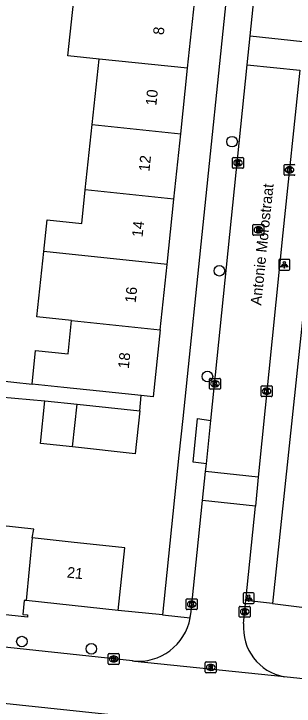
# Model space of a CAD drawing. Extents: x 163010 to 163853, y 382793 to 383982.
# Drawn here: x 163283.3 to 163309.2, y 383329.7 to 383393.8 of the extents above; entities that cross this region are included whole.
import ezdxf

# ---------------------------------------------------------------- set-up
doc = ezdxf.new("R2010")
doc.units = 0
for name, color, linetype in [('IMGEO_Boom', 7, 'Continuous'), ('IMGEO_Kolk', 7, 'Continuous'), ('IMGEO_Lichtpunt', 7, 'Continuous'), ('IMGEO_Openbare_ruimte_label', 7, 'Continuous'), ('IMGEO_Pand', 7, 'Continuous'), ('IMGEO_Pand_nummerreeks', 7, 'Continuous'), ('IMGEO_Rijbaan_lokaal_open', 7, 'Continuous'), ('IMGEO_Rioolput', 7, 'Continuous'), ('IMGEO_Voetpad_open', 7, 'Continuous')]:
    doc.layers.add(name, color=color, linetype=linetype)

msp = doc.modelspace()

# ---------------------------------------------------------------- linework, layer by layer
at = {"layer": 'IMGEO_Boom'}
for centre in [(163303.477, 383381.978), (163302.304, 383370.024), (163301.197, 383360.239), (163284.048, 383335.699), (163290.47, 383335.026)]:
    msp.add_circle(centre, 0.489, dxfattribs=at)
at = {"layer": 'IMGEO_Kolk'}
for p, q in [((163303.6, 383380.516), (163304.452, 383380.516)), ((163303.525, 383379.59), (163303.525, 383380.442)), ((163304.013, 383380.296), (163304.038, 383380.296)), ((163304.526, 383380.442), (163304.526, 383379.59)), ((163304.452, 383379.516), (163303.6, 383379.516)), ((163304.036, 383379.736), (163304.011, 383379.736)), ((163308.287, 383378.94), (163308.287, 383379.792)), ((163308.362, 383379.866), (163309.214, 383379.866)), ((163308.775, 383379.646), (163308.8, 383379.646)), ((163309.214, 383378.866), (163308.362, 383378.866)), ((163308.798, 383379.086), (163308.773, 383379.086)), ((163301.473, 383360.065), (163302.325, 383360.065)), ((163301.398, 383359.139), (163301.398, 383359.991)), ((163301.886, 383359.845), (163301.911, 383359.845)), ((163302.399, 383359.991), (163302.399, 383359.139)), ((163306.244, 383359.372), (163307.096, 383359.372)), ((163302.325, 383359.065), (163301.473, 383359.065)), ((163301.909, 383359.285), (163301.884, 383359.285)), ((163306.169, 383358.446), (163306.169, 383359.298)), ((163306.657, 383359.152), (163306.682, 383359.152)), ((163307.17, 383359.298), (163307.17, 383358.446)), ((163307.096, 383358.372), (163306.244, 383358.372)), ((163306.68, 383358.592), (163306.655, 383358.592)), ((163299.248, 383338.728), (163299.248, 383339.58)), ((163299.323, 383339.654), (163300.175, 383339.654)), ((163300.249, 383339.58), (163300.249, 383338.728)), ((163299.759, 383338.874), (163299.734, 383338.874)), ((163299.736, 383339.434), (163299.761, 383339.434)), ((163304.142, 383338.031), (163304.142, 383338.883)), ((163304.217, 383338.957), (163305.069, 383338.957)), ((163305.143, 383338.883), (163305.143, 383338.031)), ((163300.175, 383338.654), (163299.323, 383338.654)), ((163304.63, 383338.737), (163304.655, 383338.737)), ((163305.069, 383337.957), (163304.217, 383337.957)), ((163304.653, 383338.177), (163304.628, 383338.177)), ((163292.036, 383333.661), (163292.036, 383334.513)), ((163292.111, 383334.587), (163292.963, 383334.587)), ((163292.524, 383334.367), (163292.549, 383334.367)), ((163293.037, 383334.513), (163293.037, 383333.661)), ((163292.547, 383333.807), (163292.522, 383333.807)), ((163292.963, 383333.587), (163292.111, 383333.587))]:
    msp.add_line(p, q, dxfattribs=at)
for points in [[(163303.6, 383380.516), (163304.452, 383380.516)], [(163303.525, 383379.59), (163303.525, 383380.442)], [(163303.846, 383380.216), (163303.969, 383380.216), (163303.969, 383380.065), (163304.099, 383380.216), (163304.263, 383380.216), (163304.117, 383380.065), (163304.27, 383379.816), (163304.118, 383379.816), (163304.033, 383379.98), (163303.969, 383379.913), (163303.969, 383379.816), (163303.846, 383379.816), (163303.846, 383380.216)], [(163304.526, 383380.442), (163304.526, 383379.59)], [(163304.452, 383379.516), (163303.6, 383379.516)], [(163308.287, 383378.94), (163308.287, 383379.792)], [(163308.362, 383379.866), (163309.214, 383379.866)], [(163308.608, 383379.566), (163308.731, 383379.566), (163308.731, 383379.415), (163308.861, 383379.566), (163309.025, 383379.566), (163308.879, 383379.415), (163309.032, 383379.166), (163308.88, 383379.166), (163308.795, 383379.33), (163308.731, 383379.263), (163308.731, 383379.166), (163308.608, 383379.166), (163308.608, 383379.566)], [(163309.214, 383378.866), (163308.362, 383378.866)], [(163301.473, 383360.065), (163302.325, 383360.065)], [(163301.398, 383359.139), (163301.398, 383359.991)], [(163301.719, 383359.765), (163301.842, 383359.765), (163301.842, 383359.614), (163301.972, 383359.765), (163302.136, 383359.765), (163301.99, 383359.614), (163302.143, 383359.365), (163301.991, 383359.365), (163301.906, 383359.529), (163301.842, 383359.462), (163301.842, 383359.365), (163301.719, 383359.365), (163301.719, 383359.765)], [(163302.399, 383359.991), (163302.399, 383359.139)], [(163306.244, 383359.372), (163307.096, 383359.372)], [(163302.325, 383359.065), (163301.473, 383359.065)], [(163306.169, 383358.446), (163306.169, 383359.298)], [(163306.49, 383359.072), (163306.613, 383359.072), (163306.613, 383358.921), (163306.743, 383359.072), (163306.907, 383359.072), (163306.761, 383358.921), (163306.914, 383358.672), (163306.762, 383358.672), (163306.677, 383358.836), (163306.613, 383358.769), (163306.613, 383358.672), (163306.49, 383358.672), (163306.49, 383359.072)], [(163307.17, 383359.298), (163307.17, 383358.446)], [(163307.096, 383358.372), (163306.244, 383358.372)], [(163299.248, 383338.728), (163299.248, 383339.58)], [(163299.323, 383339.654), (163300.175, 383339.654)], [(163300.249, 383339.58), (163300.249, 383338.728)], [(163299.569, 383339.354), (163299.692, 383339.354), (163299.692, 383339.203), (163299.822, 383339.354), (163299.986, 383339.354), (163299.84, 383339.203), (163299.993, 383338.954), (163299.841, 383338.954), (163299.756, 383339.118), (163299.692, 383339.051), (163299.692, 383338.954), (163299.569, 383338.954), (163299.569, 383339.354)], [(163304.142, 383338.031), (163304.142, 383338.883)], [(163304.217, 383338.957), (163305.069, 383338.957)], [(163305.143, 383338.883), (163305.143, 383338.031)], [(163300.175, 383338.654), (163299.323, 383338.654)], [(163304.463, 383338.657), (163304.586, 383338.657), (163304.586, 383338.506), (163304.716, 383338.657), (163304.88, 383338.657), (163304.734, 383338.506), (163304.887, 383338.257), (163304.735, 383338.257), (163304.65, 383338.421), (163304.586, 383338.354), (163304.586, 383338.257), (163304.463, 383338.257), (163304.463, 383338.657)], [(163305.069, 383337.957), (163304.217, 383337.957)], [(163292.036, 383333.661), (163292.036, 383334.513)], [(163292.111, 383334.587), (163292.963, 383334.587)], [(163293.037, 383334.513), (163293.037, 383333.661)], [(163292.357, 383334.287), (163292.48, 383334.287), (163292.48, 383334.136), (163292.61, 383334.287), (163292.774, 383334.287), (163292.628, 383334.136), (163292.781, 383333.887), (163292.629, 383333.887), (163292.544, 383334.051), (163292.48, 383333.984), (163292.48, 383333.887), (163292.357, 383333.887), (163292.357, 383334.287)], [(163292.963, 383333.587), (163292.111, 383333.587)]]:
    msp.add_lwpolyline(points, dxfattribs=at)
for centre, start, end in [((163303.602, 383380.44), 91.55205, 178.44795), ((163303.602, 383380.44), 91.55205, 178.44795), ((163304.45, 383380.44), 1.55205, 88.44795), ((163304.45, 383380.44), 1.55205, 88.44795), ((163303.602, 383379.592), 181.55205, 268.44795), ((163303.602, 383379.592), 181.55205, 268.44795), ((163304.45, 383379.592), 271.55205, 358.44795), ((163304.45, 383379.592), 271.55205, 358.44795), ((163308.364, 383379.79), 91.55205, 178.44795), ((163308.364, 383379.79), 91.55205, 178.44795), ((163309.212, 383379.79), 1.55205, 88.44795), ((163309.212, 383379.79), 1.55205, 88.44795), ((163308.364, 383378.942), 181.55205, 268.44795), ((163308.364, 383378.942), 181.55205, 268.44795), ((163309.212, 383378.942), 271.55205, 358.44795), ((163309.212, 383378.942), 271.55205, 358.44795), ((163301.475, 383359.989), 91.55205, 178.44795), ((163301.475, 383359.989), 91.55205, 178.44795), ((163302.323, 383359.989), 1.55205, 88.44795), ((163302.323, 383359.989), 1.55205, 88.44795), ((163306.246, 383359.296), 91.55205, 178.44795), ((163306.246, 383359.296), 91.55205, 178.44795), ((163307.094, 383359.296), 1.55205, 88.44795), ((163307.094, 383359.296), 1.55205, 88.44795), ((163301.475, 383359.141), 181.55205, 268.44795), ((163301.475, 383359.141), 181.55205, 268.44795), ((163302.323, 383359.141), 271.55205, 358.44795), ((163302.323, 383359.141), 271.55205, 358.44795), ((163306.246, 383358.448), 181.55205, 268.44795), ((163306.246, 383358.448), 181.55205, 268.44795), ((163307.094, 383358.448), 271.55205, 358.44795), ((163307.094, 383358.448), 271.55205, 358.44795), ((163299.325, 383339.578), 91.55205, 178.44795), ((163299.325, 383339.578), 91.55205, 178.44795), ((163300.173, 383339.578), 1.55205, 88.44795), ((163300.173, 383339.578), 1.55205, 88.44795), ((163304.219, 383338.881), 91.55205, 178.44795), ((163304.219, 383338.881), 91.55205, 178.44795), ((163305.067, 383338.881), 1.55205, 88.44795), ((163305.067, 383338.881), 1.55205, 88.44795), ((163299.325, 383338.73), 181.55205, 268.44795), ((163299.325, 383338.73), 181.55205, 268.44795), ((163300.173, 383338.73), 271.55205, 358.44795), ((163300.173, 383338.73), 271.55205, 358.44795), ((163304.219, 383338.033), 181.55205, 268.44795), ((163304.219, 383338.033), 181.55205, 268.44795), ((163305.067, 383338.033), 271.55205, 358.44795), ((163305.067, 383338.033), 271.55205, 358.44795), ((163292.113, 383334.511), 91.55205, 178.44795), ((163292.113, 383334.511), 91.55205, 178.44795), ((163292.961, 383334.511), 1.55205, 88.44795), ((163292.961, 383334.511), 1.55205, 88.44795), ((163292.113, 383333.663), 181.55205, 268.44795), ((163292.113, 383333.663), 181.55205, 268.44795), ((163292.961, 383333.663), 271.55205, 358.44795), ((163292.961, 383333.663), 271.55205, 358.44795)]:
    msp.add_arc(centre, 0.0765, start, end, dxfattribs=at)
for centre, major_axis, ratio, start_param, end_param in [((163304.012, 383380.016), (-0.387, 0.002), 0.722429, 4.712389, 7.853982), ((163304.037, 383380.016), (-0.39, 0.002), 0.717154, 1.570796, 4.712389), ((163308.774, 383379.366), (-0.387, 0.002), 0.722429, 4.712389, 7.853982), ((163308.799, 383379.366), (-0.39, 0.002), 0.717154, 1.570796, 4.712389), ((163301.885, 383359.565), (-0.387, 0.002), 0.722429, 4.712389, 7.853982), ((163301.91, 383359.565), (-0.39, 0.002), 0.717154, 1.570796, 4.712389), ((163306.656, 383358.872), (-0.387, 0.002), 0.722429, 4.712389, 7.853982), ((163306.681, 383358.872), (-0.39, 0.002), 0.717154, 1.570796, 4.712389), ((163299.735, 383339.154), (-0.387, 0.002), 0.722429, 4.712389, 7.853982), ((163299.76, 383339.154), (-0.39, 0.002), 0.717154, 1.570796, 4.712389), ((163304.629, 383338.457), (-0.387, 0.002), 0.722429, 4.712389, 7.853982), ((163304.654, 383338.457), (-0.39, 0.002), 0.717154, 1.570796, 4.712389), ((163292.523, 383334.087), (-0.387, 0.002), 0.722429, 4.712389, 7.853982), ((163292.548, 383334.087), (-0.39, 0.002), 0.717154, 1.570796, 4.712389)]:
    msp.add_ellipse(centre, major_axis=major_axis, ratio=ratio, start_param=start_param, end_param=end_param, dxfattribs=at)
at = {"layer": 'IMGEO_Lichtpunt'}
for p, q in [((163307.812, 383370.986), (163307.812, 383370.179)), ((163307.812, 383370.986), (163307.812, 383370.179)), ((163308.714, 383371.081), (163307.906, 383371.081)), ((163308.714, 383371.081), (163307.906, 383371.081)), ((163308.808, 383370.179), (163308.808, 383370.986)), ((163308.808, 383370.179), (163308.808, 383370.986)), ((163307.906, 383370.085), (163308.714, 383370.085)), ((163307.906, 383370.085), (163308.714, 383370.085)), ((163305.418, 383340.207), (163304.61, 383340.207)), ((163305.418, 383340.207), (163304.61, 383340.207)), ((163304.516, 383340.112), (163304.516, 383339.305)), ((163304.516, 383340.112), (163304.516, 383339.305)), ((163305.512, 383339.305), (163305.512, 383340.112)), ((163305.512, 383339.305), (163305.512, 383340.112)), ((163304.61, 383339.211), (163305.418, 383339.211)), ((163304.61, 383339.211), (163305.418, 383339.211))]:
    msp.add_line(p, q, dxfattribs=at)
for points in [[(163308.186, 383370.65), (163308.225, 383370.622), (163308.037, 383370.36), (163307.999, 383370.387), (163308.186, 383370.65)], [(163308.288, 383370.602), (163308.335, 383370.602), (163308.335, 383370.28), (163308.288, 383370.28), (163308.288, 383370.602)], [(163308.398, 383370.622), (163308.436, 383370.649), (163308.623, 383370.387), (163308.584, 383370.359), (163308.398, 383370.622)], [(163304.89, 383339.776), (163304.929, 383339.748), (163304.741, 383339.486), (163304.703, 383339.513), (163304.89, 383339.776)], [(163304.992, 383339.728), (163305.039, 383339.728), (163305.039, 383339.406), (163304.992, 383339.406), (163304.992, 383339.728)], [(163305.102, 383339.748), (163305.14, 383339.775), (163305.327, 383339.513), (163305.288, 383339.485), (163305.102, 383339.748)]]:
    msp.add_lwpolyline(points, dxfattribs=at)
for centre in [(163308.311, 383370.784), (163305.015, 383339.91)]:
    msp.add_circle(centre, 0.0994, dxfattribs=at)
for centre, start, end in [((163307.906, 383370.986), 90, 180), ((163307.906, 383370.986), 90, 180), ((163308.714, 383370.986), 0, 90), ((163308.714, 383370.986), 0, 90), ((163307.906, 383370.179), 180, 270), ((163307.906, 383370.179), 180, 270), ((163308.714, 383370.179), 270, 0), ((163308.714, 383370.179), 270, 360), ((163304.61, 383340.112), 90, 180), ((163304.61, 383340.112), 90, 180), ((163305.418, 383340.112), 0, 90), ((163305.418, 383340.112), 0, 90), ((163304.61, 383339.305), 180, 270), ((163304.61, 383339.305), 180, 270), ((163305.418, 383339.305), 270, 0), ((163305.418, 383339.305), 270, 360)]:
    msp.add_arc(centre, 0.0946, start, end, dxfattribs=at)
at = {"layer": 'IMGEO_Pand'}
for points in [[(163291.178, 383389.627), (163288.303, 383389.928), (163288.936, 383395.981), (163291.811, 383395.68)], [(163299.372, 383388.769), (163300.005, 383394.823)], [(163290.544, 383383.572), (163291.178, 383389.627)], [(163299.372, 383388.769), (163291.178, 383389.627)], [(163298.739, 383382.715), (163299.372, 383388.769)], [(163289.911, 383377.518), (163290.544, 383383.572)], [(163290.544, 383383.572), (163298.739, 383382.715)], [(163298.105, 383376.661), (163298.739, 383382.715)], [(163286.065, 383371.8), (163286.372, 383374.737), (163289.584, 383374.396), (163289.911, 383377.518)], [(163298.105, 383376.661), (163289.911, 383377.518)], [(163297.472, 383370.607), (163298.105, 383376.661)], [(163288.644, 383365.413), (163285.432, 383365.754), (163286.065, 383371.8)], [(163297.472, 383370.607), (163286.065, 383371.8)], [(163296.839, 383364.553), (163297.472, 383370.607)], [(163284.994, 383359.523), (163285.32, 383362.639), (163288.321, 383362.325), (163288.644, 383365.413)], [(163288.644, 383365.413), (163296.839, 383364.553)], [(163296.839, 383364.553), (163296.19, 383358.352), (163295.087, 383358.467)], [(163295.087, 383358.467), (163291.218, 383358.872), (163287.927, 383359.216), (163284.994, 383359.523)], [(163288.732, 383353.711), (163285.755, 383354.03), (163286.179, 383357.987)], [(163286.179, 383357.987), (163289.157, 383357.667)], [(163288.732, 383353.711), (163289.157, 383357.667)], [(163289.157, 383357.667), (163294.938, 383357.047)], [(163294.938, 383357.047), (163294.514, 383353.09), (163288.732, 383353.711)], [(163284.999, 383345.286), (163285.139, 383346.108), (163282.029, 383346.442), (163282.25, 383348.497), (163279.275, 383348.817)], [(163284.999, 383345.286), (163284.453, 383339.494)], [(163292.958, 383338.581), (163293.579, 383344.373), (163288.608, 383344.907), (163284.999, 383345.286)], [(163284.453, 383339.494), (163284.273, 383339.513), (163284.134, 383338.216), (163284.578, 383338.169), (163284.557, 383337.97), (163278.181, 383338.643)], [(163292.958, 383338.581), (163284.453, 383339.494)]]:
    msp.add_lwpolyline(points, dxfattribs=at)
at = {"layer": 'IMGEO_Rijbaan_lokaal_open'}
for points in [[(163305.156, 383391.761), (163307.263, 383412.38)], [(163304.884, 383389.094), (163305.156, 383391.761)], [(163305.156, 383391.761), (163310.031, 383391.258)], [(163301.52, 383356.168), (163304.884, 383389.094)], [(163304.884, 383389.094), (163309.75, 383388.592)], [(163309.75, 383388.592), (163308.166, 383373.531), (163305.903, 383350.922)], [(163301.102, 383352.16), (163301.52, 383356.168)], [(163301.028, 383351.445), (163301.102, 383352.16)], [(163300.748, 383348.76), (163301.028, 383351.445)], [(163305.903, 383350.922), (163301.028, 383351.445)], [(163305.903, 383350.922), (163305.634, 383348.236)], [(163299.653, 383338.244), (163300.748, 383348.76)], [(163305.634, 383348.236), (163300.748, 383348.76)], [(163304.759, 383339.49), (163305.634, 383348.236)], [(163304.546, 383337.367), (163304.759, 383339.49)], [(163294.277, 383333.901), (163264.838, 383337.06)], [(163308.306, 383332.445), (163294.491, 383333.86), (163294.277, 383333.901)], [(163325.729, 383330.567), (163308.306, 383332.445)], [(163264.288, 383331.894), (163342.345, 383323.645)]]:
    msp.add_lwpolyline(points, dxfattribs=at)
for centre, radius, start, end in [((163295.535, 383338.66), 4.139, 349.45443, 354.23846), ((163294.795, 383338.759), 4.885, 263.91733, 349.90159), ((163309.125, 383336.968), 4.597, 175.02223, 259.73142)]:
    msp.add_arc(centre, radius, start, end, dxfattribs=at)
at = {"layer": 'IMGEO_Rioolput'}
for p, q in [((163305.408, 383373.383), (163305.408, 383374.235)), ((163305.483, 383374.309), (163306.335, 383374.309)), ((163306.409, 383374.235), (163306.409, 383373.383)), ((163305.919, 383373.529), (163305.894, 383373.529)), ((163305.896, 383374.089), (163305.921, 383374.089)), ((163306.335, 383373.309), (163305.483, 383373.309)), ((163301.002, 383332.881), (163301.002, 383333.733)), ((163301.077, 383333.807), (163301.929, 383333.807)), ((163302.003, 383333.733), (163302.003, 383332.881)), ((163301.49, 383333.587), (163301.515, 383333.587)), ((163301.929, 383332.807), (163301.077, 383332.807)), ((163301.513, 383333.027), (163301.488, 383333.027))]:
    msp.add_line(p, q, dxfattribs=at)
for points in [[(163305.408, 383373.383), (163305.408, 383374.235)], [(163305.483, 383374.309), (163306.335, 383374.309)], [(163306.409, 383374.235), (163306.409, 383373.383)], [(163305.997, 383374.007), (163305.745, 383374.009), (163305.745, 383373.609)], [(163305.745, 383373.609), (163305.869, 383373.609), (163305.869, 383373.771), (163305.88, 383373.771)], [(163305.923, 383373.928), (163305.869, 383373.928), (163305.869, 383373.847)], [(163305.869, 383373.847), (163305.921, 383373.847)], [(163305.927, 383373.742), (163305.998, 383373.609), (163306.138, 383373.609), (163306.073, 383373.735)], [(163306.335, 383373.309), (163305.483, 383373.309)], [(163301.002, 383332.881), (163301.002, 383333.733)], [(163301.077, 383333.807), (163301.929, 383333.807)], [(163302.003, 383333.733), (163302.003, 383332.881)], [(163301.591, 383333.505), (163301.339, 383333.507), (163301.339, 383333.107)], [(163301.339, 383333.107), (163301.463, 383333.107), (163301.463, 383333.269), (163301.474, 383333.269)], [(163301.517, 383333.426), (163301.463, 383333.426), (163301.463, 383333.345)], [(163301.463, 383333.345), (163301.515, 383333.345)], [(163301.521, 383333.24), (163301.592, 383333.107), (163301.732, 383333.107), (163301.667, 383333.233)], [(163301.929, 383332.807), (163301.077, 383332.807)]]:
    msp.add_lwpolyline(points, dxfattribs=at)
for centre, radius, start, end in [((163305.485, 383374.233), 0.0765, 91.55205, 178.44795), ((163305.485, 383374.233), 0.0765, 91.55205, 178.44795), ((163306.333, 383374.233), 0.0765, 1.55205, 88.44795), ((163306.333, 383374.233), 0.0765, 1.55205, 88.44795), ((163305.879, 383373.718), 0.0533, 26.02933, 88.69889), ((163305.905, 383374.036), 0.19, 274.7715, 282.96867), ((163305.929, 383373.832), 0.0964, 77.00612, 93.18647), ((163305.943, 383373.889), 0.0378, 276.66336, 79.67722), ((163305.996, 383373.897), 0.109, 350.36119, 89.41601), ((163305.994, 383373.897), 0.112, 277.58423, 350.98172), ((163305.978, 383373.682), 0.108, 29.51342, 73.79051), ((163305.485, 383373.385), 0.0765, 181.55205, 268.44795), ((163305.485, 383373.385), 0.0765, 181.55205, 268.44795), ((163306.333, 383373.385), 0.0765, 271.55205, 358.44795), ((163306.333, 383373.385), 0.0765, 271.55205, 358.44795), ((163301.079, 383333.731), 0.0765, 91.55205, 178.44795), ((163301.079, 383333.731), 0.0765, 91.55205, 178.44795), ((163301.927, 383333.731), 0.0765, 1.55205, 88.44795), ((163301.927, 383333.731), 0.0765, 1.55205, 88.44795), ((163301.473, 383333.216), 0.0533, 26.02933, 88.69889), ((163301.499, 383333.534), 0.19, 274.7715, 282.96867), ((163301.523, 383333.33), 0.0964, 77.00612, 93.18647), ((163301.537, 383333.387), 0.0378, 276.66336, 79.67722), ((163301.59, 383333.395), 0.109, 350.36119, 89.41601), ((163301.588, 383333.395), 0.112, 277.58423, 350.98172), ((163301.572, 383333.18), 0.108, 29.51342, 73.79051), ((163301.079, 383332.883), 0.0765, 181.55205, 268.44795), ((163301.079, 383332.883), 0.0765, 181.55205, 268.44795), ((163301.927, 383332.883), 0.0765, 271.55205, 358.44795), ((163301.927, 383332.883), 0.0765, 271.55205, 358.44795)]:
    msp.add_arc(centre, radius, start, end, dxfattribs=at)
for centre, major_axis, ratio, start_param, end_param in [((163305.895, 383373.809), (-0.387, 0.002), 0.722429, 4.712389, 7.853982), ((163305.92, 383373.809), (-0.39, 0.002), 0.717154, 1.570796, 4.712389), ((163301.489, 383333.307), (-0.387, 0.002), 0.722429, 4.712389, 7.853982), ((163301.514, 383333.307), (-0.39, 0.002), 0.717154, 1.570796, 4.712389)]:
    msp.add_ellipse(centre, major_axis=major_axis, ratio=ratio, start_param=start_param, end_param=end_param, dxfattribs=at)
at = {"layer": 'IMGEO_Voetpad_open'}
for points in [[(163304.748, 383412.836), (163298.917, 383356.341), (163298.569, 383352.966), (163297.041, 383338.164)], [(163315.002, 383413.086), (163307.22, 383339.213)], [(163276.754, 383360.384), (163278.201, 383360.266), (163284.994, 383359.523)], [(163279.217, 383358.61), (163286.179, 383357.987)], [(163294.938, 383357.047), (163295.087, 383358.467)], [(163301.102, 383352.16), (163299.891, 383352.299), (163300.275, 383356.347), (163301.52, 383356.168)], [(163307.22, 383339.213), (163304.759, 383339.49)], [(163307.22, 383339.213), (163310.415, 383338.833), (163310.447, 383337.492), (163311.127, 383336.058), (163311.764, 383335.591), (163312.502, 383335.31), (163326.858, 383333.74), (163327.127, 383336.98)], [(163297.041, 383338.164), (163292.958, 383338.581)], [(163297.041, 383338.164), (163299.604, 383337.902)]]:
    msp.add_lwpolyline(points, dxfattribs=at)

# ---------------------------------------------------------------- texts
at = {"layer": 'IMGEO_Openbare_ruimte_label'}
msp.add_text('Antonie Morostraat', height=1, rotation=84.14691, dxfattribs=at).set_placement((163306.167, 383366.791))
at = {"layer": 'IMGEO_Pand_nummerreeks'}
for s, rotation, p in [('8', 84.02999, (163297.157, 383391.818)), ('10', 84.02813, (163296.473, 383385.274)), ('12', 84.02813, (163295.836, 383379.181)), ('14', 84.02813, (163295.199, 383373.098)), ('16', 84.02813, (163294.563, 383367.012)), ('18', 84.02999, (163293.926, 383360.929)), ('21', 353.87495, (163288.176, 383341.628))]:
    msp.add_text(s, height=1, rotation=rotation, dxfattribs=at).set_placement(p)

doc.saveas('drawing.dxf')
